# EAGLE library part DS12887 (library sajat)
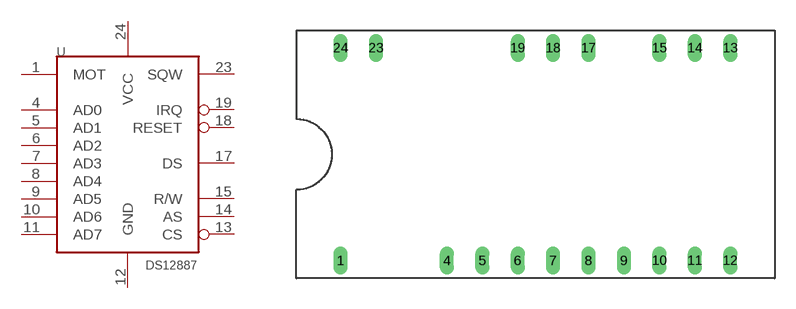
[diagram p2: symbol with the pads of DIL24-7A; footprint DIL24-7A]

Designator prefix -

## DS12887  [DIL24-7A]
1  MOT  in
4  AD0
5  AD1
6  AD2
7  AD3
8  AD4
9  AD5
10  AD6
11  AD7
12  GND  pwr
13  CS
14  AS
15  R/W
17  DS
18  RESET
19  IRQ
23  SQW
24  VCC  pwr

## Footprint DIL24-7A (pad centres in mm)
drill 0.254 pad 1.016 long: 1 -13.97,-7.62; 4 -6.35,-7.62; 5 -3.81,-7.62; 6 -1.27,-7.62; 7 1.27,-7.62; 8 3.81,-7.62; 9 6.35,-7.62; 10 8.89,-7.62; 11 11.43,-7.62; 12 13.97,-7.62; 13 13.97,7.62; 14 11.43,7.62; 15 8.89,7.62; 17 3.81,7.62; 18 1.27,7.62; 19 -1.27,7.62; 23 -11.43,7.62; 24 -13.97,7.62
